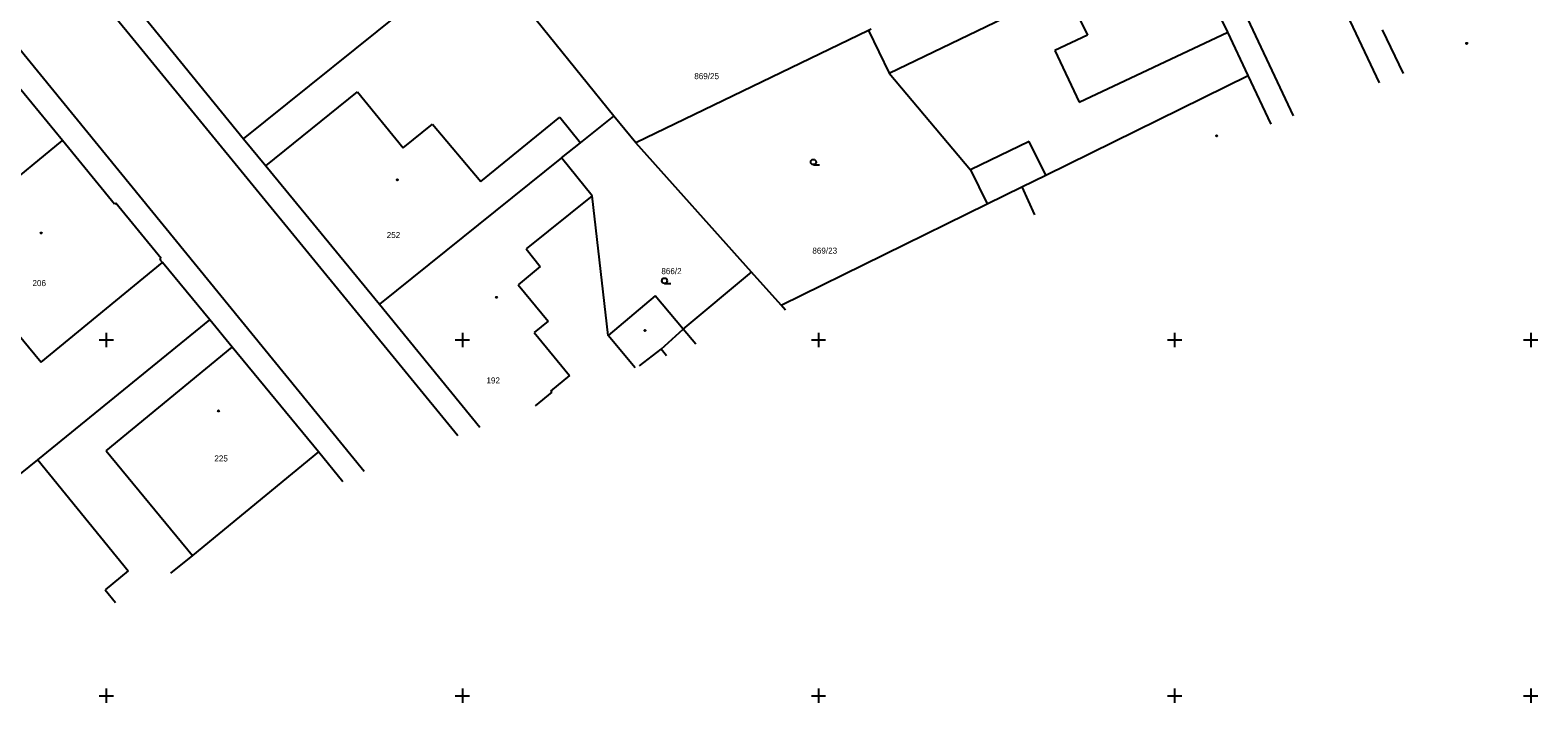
# Model space of a CAD drawing. Extents: x -711081 to -709338, y -1025122 to -1024092.
# Drawn here: x -710805.3 to -710699.5, y -1025025.5 to -1024978.2 of the extents above; entities that cross this region are included whole.
import ezdxf

# ---------------------------------------------------------------- set-up
doc = ezdxf.new("R2010")
doc.units = 0
for name, color, linetype in [('Z_hektometricka_sit', 7, 'Continuous'), ('Z_katastr_cisla_pozemkova', 7, 'Continuous'), ('Z_katastr_cisla_stavebni', 7, 'Continuous'), ('Z_katastr_hranice', 7, 'Continuous'), ('Z_katastr_vnitrni_kresba', 7, 'Continuous'), ('Z_katastr_znacky_budov', 7, 'Continuous'), ('Z_katastr_znacky_kultur', 7, 'Continuous')]:
    doc.layers.add(name, color=color, linetype=linetype)

msp = doc.modelspace()

# ---------------------------------------------------------------- linework, layer by layer
at = {"layer": 'Z_hektometricka_sit'}
for p, q in [((-710800, -1024999.5), (-710800, -1025000.5)), ((-710775, -1024999.5), (-710775, -1025000.5)), ((-710750, -1024999.5), (-710750, -1025000.5)), ((-710725, -1024999.5), (-710725, -1025000.5)), ((-710700, -1024999.5), (-710700, -1025000.5)), ((-710800.5, -1025000), (-710799.5, -1025000)), ((-710775.5, -1025000), (-710774.5, -1025000)), ((-710750.5, -1025000), (-710749.5, -1025000)), ((-710725.5, -1025000), (-710724.5, -1025000)), ((-710700.5, -1025000), (-710699.5, -1025000)), ((-710800.5, -1025025), (-710799.5, -1025025)), ((-710800, -1025024.5), (-710800, -1025025.5)), ((-710775.5, -1025025), (-710774.5, -1025025)), ((-710775, -1025024.5), (-710775, -1025025.5)), ((-710750.5, -1025025), (-710749.5, -1025025)), ((-710750, -1025024.5), (-710750, -1025025.5)), ((-710725.5, -1025025), (-710724.5, -1025025)), ((-710725, -1025024.5), (-710725, -1025025.5)), ((-710700.5, -1025025), (-710699.5, -1025025)), ((-710700, -1025024.5), (-710700, -1025025.5))]:
    msp.add_line(p, q, dxfattribs=at)
at = {"layer": 'Z_katastr_hranice'}
for p, q in [((-710721.27, -1024978.38), (-710726, -1024968.36)), ((-710790.36, -1024985.88), (-710773.82, -1024972.56)), ((-710764.37, -1024984.27), (-710772.17, -1024974.6)), ((-710798.39, -1024975.98), (-710790.36, -1024985.88)), ((-710746.48, -1024978.26), (-710762.83, -1024986.16)), ((-710746.3, -1024978.17), (-710746.48, -1024978.26)), ((-710746.48, -1024978.26), (-710745.03, -1024981.27)), ((-710719.83, -1024981.43), (-710721.27, -1024978.38)), ((-710710.42, -1024978.21), (-710708.96, -1024981.29)), ((-710745.03, -1024981.27), (-710739.34, -1024988.05)), ((-710734.05, -1024988.43), (-710719.83, -1024981.43)), ((-710718.22, -1024984.84), (-710719.83, -1024981.43)), ((-710803.07, -1024986), (-710806.29, -1024982.05)), ((-710766.71, -1024986.15), (-710764.37, -1024984.27)), ((-710762.83, -1024986.16), (-710764.37, -1024984.27)), ((-710790.36, -1024985.88), (-710788.79, -1024987.78)), ((-710814.8, -1024995.62), (-710803.07, -1024986)), ((-710799.41, -1024990.46), (-710803.07, -1024986)), ((-710768.03, -1024987.21), (-710766.71, -1024986.15)), ((-710754.71, -1024995.24), (-710762.83, -1024986.16)), ((-710788.79, -1024987.78), (-710780.82, -1024997.48)), ((-710768.03, -1024987.21), (-710780.82, -1024997.48)), ((-710765.88, -1024989.88), (-710768.03, -1024987.21)), ((-710739.34, -1024988.05), (-710738.16, -1024990.45)), ((-710735.73, -1024989.25), (-710734.05, -1024988.43)), ((-710764.77, -1024999.68), (-710765.88, -1024989.88)), ((-710738.16, -1024990.45), (-710735.73, -1024989.25)), ((-710735.73, -1024989.25), (-710734.84, -1024991.21)), ((-710799.33, -1024990.4), (-710799.41, -1024990.46)), ((-710796.15, -1024994.28), (-710799.33, -1024990.4)), ((-710752.63, -1024997.56), (-710738.16, -1024990.45)), ((-710796.23, -1024994.34), (-710796.15, -1024994.28)), ((-710796.06, -1024994.55), (-710796.23, -1024994.34)), ((-710792.74, -1024998.6), (-710796.06, -1024994.55)), ((-710759.5, -1024999.25), (-710754.71, -1024995.24)), ((-710752.63, -1024997.56), (-710754.71, -1024995.24)), ((-710780.82, -1024997.48), (-710773.77, -1025006.12)), ((-710761.46, -1024996.91), (-710764.77, -1024999.68)), ((-710759.5, -1024999.25), (-710761.46, -1024996.91)), ((-710752.31, -1024997.9), (-710752.63, -1024997.56)), ((-710804.81, -1025008.42), (-710792.74, -1024998.6)), ((-710791.17, -1025000.5), (-710792.74, -1024998.6)), ((-710761.04, -1025000.66), (-710759.5, -1024999.25)), ((-710785.09, -1025007.86), (-710791.17, -1025000.5)), ((-710762.56, -1025001.83), (-710761.04, -1025000.66)), ((-710760.68, -1025001.11), (-710761.04, -1025000.66)), ((-710785.09, -1025007.86), (-710793.95, -1025015.15)), ((-710783.38, -1025009.96), (-710785.09, -1025007.86)), ((-710806.03, -1025009.41), (-710804.81, -1025008.42)), ((-710804.81, -1025008.42), (-710798.46, -1025016.23)), ((-710793.95, -1025015.15), (-710795.48, -1025016.39)), ((-710798.46, -1025016.23), (-710800.07, -1025017.55)), ((-710800.07, -1025017.55), (-710799.34, -1025018.45))]:
    msp.add_line(p, q, dxfattribs=at)
at = {"layer": 'Z_katastr_vnitrni_kresba'}
for p, q in [((-710736.09, -1024928.04), (-710710.64, -1024981.93)), ((-710741.85, -1024930.64), (-710716.68, -1024984.25)), ((-710812.5, -1024961.25), (-710775.33, -1025006.72)), ((-710781.9, -1025009.24), (-710820.64, -1024961.75)), ((-710733.21, -1024974.33), (-710731.12, -1024978.6)), ((-710745.03, -1024981.27), (-710735.74, -1024976.79)), ((-710731.71, -1024983.29), (-710721.27, -1024978.38)), ((-710731.12, -1024978.6), (-710733.4, -1024979.66)), ((-710733.4, -1024979.66), (-710731.71, -1024983.29)), ((-710788.79, -1024987.78), (-710782.37, -1024982.56)), ((-710782.37, -1024982.56), (-710779.16, -1024986.5)), ((-710779.16, -1024986.5), (-710777.09, -1024984.85)), ((-710777.09, -1024984.85), (-710773.71, -1024988.86)), ((-710773.71, -1024988.86), (-710768.15, -1024984.35)), ((-710768.15, -1024984.35), (-710766.71, -1024986.15)), ((-710735.22, -1024986.06), (-710739.34, -1024988.05)), ((-710734.05, -1024988.43), (-710735.22, -1024986.06)), ((-710765.88, -1024989.88), (-710770.52, -1024993.61)), ((-710770.52, -1024993.61), (-710769.53, -1024994.84)), ((-710804.58, -1025001.56), (-710796.06, -1024994.55)), ((-710769.53, -1024994.84), (-710771.08, -1024996.12)), ((-710771.08, -1024996.12), (-710768.98, -1024998.68)), ((-710806.68, -1024999.01), (-710804.58, -1025001.56)), ((-710768.98, -1024998.68), (-710769.97, -1024999.49)), ((-710769.97, -1024999.49), (-710767.49, -1025002.5)), ((-710758.61, -1025000.31), (-710759.5, -1024999.25)), ((-710800.01, -1025007.8), (-710791.17, -1025000.5)), ((-710762.87, -1025001.95), (-710764.77, -1024999.68)), ((-710767.49, -1025002.5), (-710768.81, -1025003.59)), ((-710768.73, -1025003.68), (-710769.88, -1025004.63)), ((-710768.81, -1025003.59), (-710768.73, -1025003.68)), ((-710800.01, -1025007.8), (-710793.95, -1025015.15))]:
    msp.add_line(p, q, dxfattribs=at)
at = {"layer": 'Z_katastr_znacky_budov'}
for centre in [(-710704.49, -1024979.17), (-710722.04, -1024985.66), (-710779.57, -1024988.75), (-710804.57, -1024992.49), (-710772.6, -1024997.01), (-710762.18, -1024999.34), (-710792.12, -1025004.99)]:
    msp.add_circle(centre, 0.0437, dxfattribs=at)
at = {"layer": 'Z_katastr_znacky_kultur'}
for p, q in [((-710750.36, -1024987.69), (-710749.92, -1024987.69)), ((-710760.81, -1024996.03), (-710760.37, -1024996.03))]:
    msp.add_line(p, q, dxfattribs=at)
for centre in [(-710750.36, -1024987.5), (-710760.81, -1024995.84)]:
    msp.add_circle(centre, 0.187, dxfattribs=at)

# ---------------------------------------------------------------- texts
at = {"layer": 'Z_katastr_cisla_pozemkova'}
for s, p in [('869/25', (-710758.72, -1024981.68)), ('869/23', (-710750.43, -1024993.94)), ('866/2', (-710761.03, -1024995.38))]:
    msp.add_text(s, height=0.425, dxfattribs=at).set_placement(p)
at = {"layer": 'Z_katastr_cisla_stavebni'}
for s, p in [('252', (-710780.31, -1024992.84)), ('206', (-710805.18, -1024996.22)), ('192', (-710773.31, -1025003.06)), ('225', (-710792.41, -1025008.54))]:
    msp.add_text(s, height=0.425, dxfattribs=at).set_placement(p)

doc.saveas('drawing.dxf')
